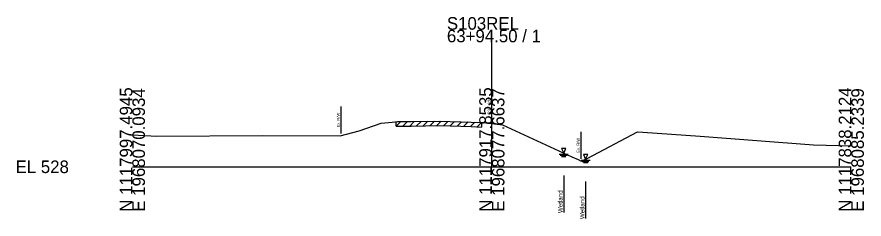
# Model space of a CAD drawing. Extents: x -26 to 163, y -10 to 24518.
# Drawn here: x -25.7 to 162.8, y 11488.4 to 11533.4 of the extents above; entities that cross this region are included whole.
import ezdxf

# ---------------------------------------------------------------- set-up
doc = ezdxf.new("R2010")
doc.units = 0
for name, color, linetype in [('RD_GPK_XS_Cell', 7, 'Continuous'), ('RD_XS_ExGround', 7, 'Continuous'), ('RD_XS_ExPaveRet', 7, 'Continuous'), ('RD_XS_ExRW', 7, 'Continuous'), ('RD_XS_EXWetland', 7, 'Continuous'), ('RD_XS_TX_Elev_EX', 7, 'Continuous')]:
    doc.layers.add(name, color=color, linetype=linetype)

msp = doc.modelspace()

# ---------------------------------------------------------------- linework, layer by layer
at = {"layer": 'RD_GPK_XS_Cell'}
for p, q in [((80, 11500), (80, 11530.53)), ((0, 11500), (80, 11500)), ((80, 11500), (160, 11500))]:
    msp.add_line(p, q, dxfattribs=at)
at = {"layer": 'RD_XS_ExGround'}
msp.add_lwpolyline([(0, 11507.13), (5.41, 11506.85), (28.98, 11506.95), (46.26, 11506.87), (50.44, 11508.02), (55.39, 11509.69), (57.83, 11509.93), (59.03, 11510.06), (62.05, 11510.07), (68.45, 11510.18), (75.37, 11509.96), (78.03, 11509.84), (79.22, 11509.73), (80, 11509.63), (82.36, 11509.34), (97.83, 11502.2), (99.21, 11501.65), (99.88, 11501.23), (101.2, 11501.87), (112.4, 11507.77), (113.64, 11507.74), (126.36, 11506.84), (151.59, 11504.91), (160, 11504.66)], dxfattribs=at)
at = {"layer": 'RD_XS_ExPaveRet'}
for p, q in [((58.72, 11509.02), (59.76, 11510.06)), ((58.72, 11509.02), (58.72, 11510.02)), ((60.22, 11509.06), (61.23, 11510.07)), ((61.73, 11509.07), (62.74, 11510.08)), ((63.23, 11509.09), (64.25, 11510.11)), ((64.73, 11509.11), (65.75, 11510.13)), ((66.23, 11509.14), (67.25, 11510.16)), ((67.74, 11509.17), (68.74, 11510.17)), ((69.24, 11509.15), (70.21, 11510.12)), ((70.74, 11509.1), (71.72, 11510.07)), ((72.25, 11509.06), (73.22, 11510.03)), ((73.75, 11509.01), (74.72, 11509.98)), ((75.25, 11508.96), (76.22, 11509.92)), ((58.72, 11509.02), (59.03, 11509.06)), ((59.03, 11509.06), (62.05, 11509.07)), ((62.05, 11509.07), (68.45, 11509.18)), ((68.45, 11509.18), (75.37, 11508.96)), ((75.37, 11508.96), (77.73, 11508.86)), ((76.76, 11508.9), (77.72, 11509.86)), ((77.73, 11509.86), (77.73, 11508.86))]:
    msp.add_line(p, q, dxfattribs=at)
at = {"layer": 'RD_XS_ExRW'}
for p, q in [((46.41, 11513.41), (46.41, 11507.41)), ((99.78, 11507.8), (99.78, 11501.8))]:
    msp.add_line(p, q, dxfattribs=at)
at = {"layer": 'RD_XS_EXWetland'}
for p, q in [((94.99, 11502.8), (96.99, 11502.8)), ((94.99, 11502.8), (96.99, 11502.8)), ((95.24, 11502.55), (96.74, 11502.55)), ((95.24, 11502.55), (96.74, 11502.55)), ((95.49, 11504.05), (95.99, 11503.05)), ((96.49, 11504.05), (95.49, 11504.05)), ((95.49, 11504.05), (95.99, 11503.05)), ((96.49, 11504.05), (95.49, 11504.05)), ((95.99, 11503.05), (96.49, 11504.05)), ((95.99, 11503.05), (96.49, 11504.05)), ((100.37, 11502.71), (100.87, 11501.71)), ((101.37, 11502.71), (100.37, 11502.71)), ((100.37, 11502.71), (100.87, 11501.71)), ((101.37, 11502.71), (100.37, 11502.71)), ((100.87, 11501.71), (101.37, 11502.71)), ((100.87, 11501.71), (101.37, 11502.71)), ((95.49, 11502.3), (96.49, 11502.3)), ((95.49, 11502.3), (96.49, 11502.3)), ((99.87, 11501.46), (101.87, 11501.46)), ((99.87, 11501.46), (101.87, 11501.46)), ((100.12, 11501.21), (101.62, 11501.21)), ((100.12, 11501.21), (101.62, 11501.21)), ((100.37, 11500.96), (101.37, 11500.96)), ((100.37, 11500.96), (101.37, 11500.96)), ((95.99, 11498.05), (95.99, 11489.8)), ((95.99, 11498.05), (95.99, 11489.8)), ((100.87, 11496.71), (100.87, 11488.46)), ((100.87, 11496.71), (100.87, 11488.46))]:
    msp.add_line(p, q, dxfattribs=at)

# ---------------------------------------------------------------- texts
at = {"layer": 'RD_GPK_XS_Cell'}
for s, p in [('S103REL', (70, 11530.53)), ('63+94.50 / 1', (70, 11527.73)), ('EL 528', (-26, 11498.6))]:
    msp.add_text(s, height=2.8, dxfattribs=at).set_placement(p)
for s, p in [('N 1117997.4945', (0, 11490)), ('N 1117917.8535', (80, 11490)), ('N 1117838.2124', (160, 11490)), ('E 1968070.0934', (2.8, 11490)), ('E 1968077.6637', (82.8, 11490)), ('E 1968085.2339', (162.8, 11490))]:
    msp.add_text(s, height=2.8, rotation=90, dxfattribs=at).set_placement(p)
at = {"layer": 'RD_XS_ExRW'}
for p in [(46.16, 11508.75), (99.53, 11503.14)]:
    msp.add_text('Ex. R/W ', height=0.65, rotation=90, dxfattribs=at).set_placement(p)
at = {"layer": 'RD_XS_EXWetland'}
for p in [(95.74, 11489.69), (95.74, 11489.69), (100.62, 11488.35), (100.62, 11488.35)]:
    msp.add_text('Wetland ', height=1, rotation=90, dxfattribs=at).set_placement(p)
at = {"layer": 'RD_XS_TX_Elev_EX'}
msp.add_text('537.63', height=0.8, rotation=90, dxfattribs=at).set_placement((79.9, 11511.63))

doc.saveas('drawing.dxf')
